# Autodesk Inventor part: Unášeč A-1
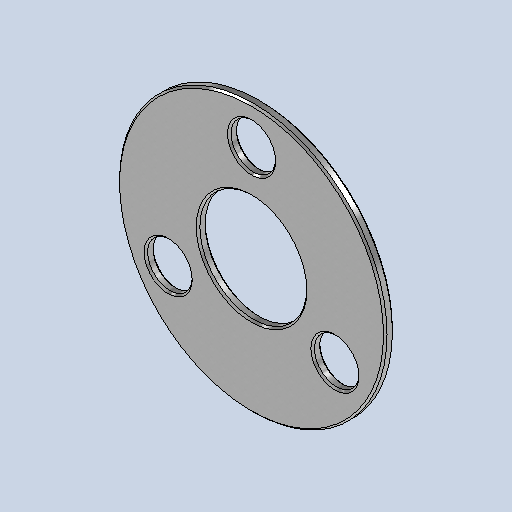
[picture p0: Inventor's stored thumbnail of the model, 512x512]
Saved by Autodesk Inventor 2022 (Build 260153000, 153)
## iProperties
Created: 2025-05
Part Number: Unášeč A-1
Material: Všeobecné
Document SubType Name: Modeling
Designer: jbart
Density: 1 g/cm^3
Appearance: Broušená
Mass: 527.643 g
Surface Area: 1207.14 cm^2
Volume: 527.643 cm^3
Author: jbart
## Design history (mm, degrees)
sketch "Náčrt1"
  geometry: L1 (0, 108)-(93.531, -54); L2 (93.531, -54)-(-93.531, -54); L3 (-93.531, -54)-(0, 108); L4 (0, 108)-(0, 0); L5 (0, 0)-(93.531, -54); L6 (0, 0)-(-93.531, -54); C1 r 25 at (0, 108); C2 r 25 at (-93.531, -54); C3 r 25 at (93.531, -54); C4 r 150 at (0, 0); C5 r 60 at (0, 0); 1 further point
  constraints: 12 end point, 6 coincident, 5 centre point, 1 vertical, 7 other
  dimensions: "d0" = 108 distance of L4.end L1.end; "d1" = 50 diameter of C1; "d2" = 50 diameter of C2; "d3" = 50 diameter of C3; "d4" = 300 diameter of C4; "d7" = 120 diameter of C5
extrude "Vysunutí2" new body sketch "Náčrt1" distance "d8" = 10; taper "d9" = 0 deg
chamfer "Zkosení1" distance "d10" = 2; stored, may be unused: second distance "d11" = 2, angle "d12" = 45 deg
node "Těleso2"
